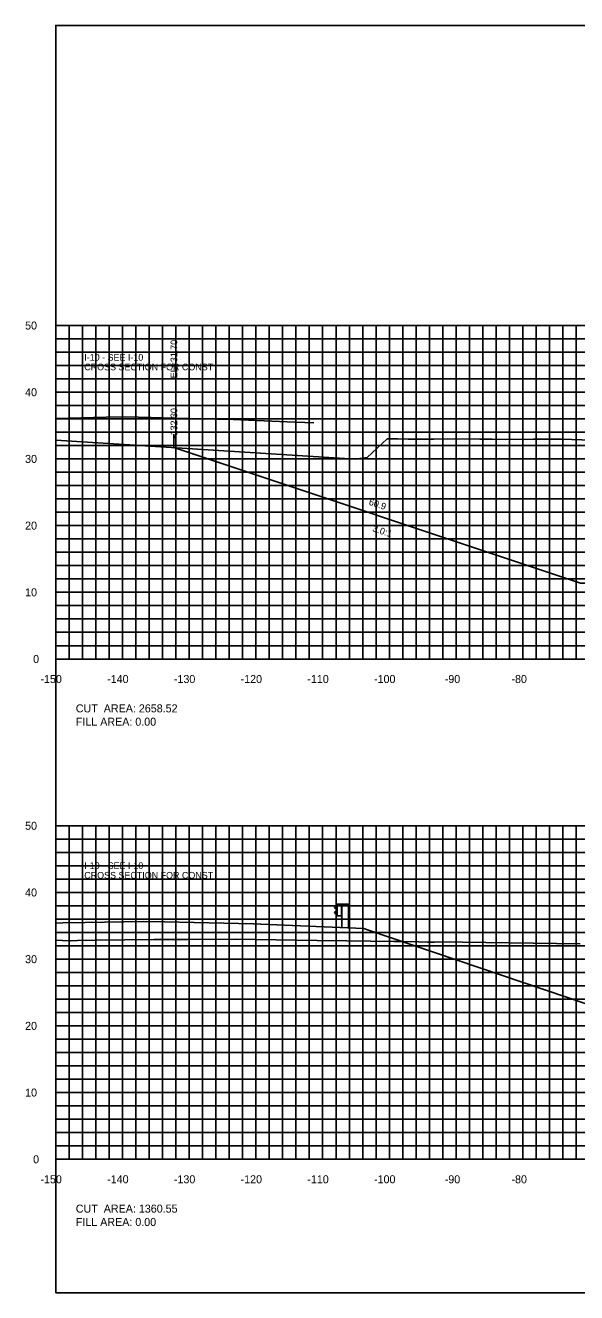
# Model space of a CAD drawing. Extents: x 1800976 to 1805104, y 250057 to 250580.
# Drawn here: x 1804176.4 to 1804259.1, y 250079.4 to 250269.4 of the extents above; entities that cross this region are included whole.
import ezdxf

# ---------------------------------------------------------------- set-up
doc = ezdxf.new("R2010")
doc.units = 0
for name, color, linetype in [('10', 7, 'Continuous'), ('3', 7, 'Continuous'), ('31', 7, 'Continuous'), ('4', 7, 'Continuous'), ('60', 7, 'Continuous'), ('ANNO-TXT', 7, 'Continuous'), ('CL-CNST', 7, 'Continuous'), ('Level 1', 7, 'Continuous'), ('Level 62', 7, 'Continuous'), ('M-ROADS', 7, 'Continuous')]:
    doc.layers.add(name, color=color, linetype=linetype)

msp = doc.modelspace()

# ---------------------------------------------------------------- linework, layer by layer
msp.add_line((1804198.7, 250206.13), (1804198.7, 250208.13))
msp.add_lwpolyline([(1804181, 250079.43), (1804481, 250079.43), (1804481, 250269.43), (1804181, 250269.43)], close=True)
at = {"layer": '60'}
for p, q in [((1804180.94, 250224.43), (1804181, 250224.43)), ((1804181, 250174.43), (1804181, 250224.43)), ((1804180.94, 250214.43), (1804181, 250214.43)), ((1804180.94, 250204.43), (1804181, 250204.43)), ((1804180.94, 250194.43), (1804181, 250194.43)), ((1804180.94, 250184.43), (1804181, 250184.43)), ((1804180.94, 250174.43), (1804181, 250174.43)), ((1804181, 250174.43), (1804481, 250174.43)), ((1804181, 250174.37), (1804181, 250174.43)), ((1804191, 250174.37), (1804191, 250174.43)), ((1804201, 250174.37), (1804201, 250174.43)), ((1804211, 250174.37), (1804211, 250174.43)), ((1804221, 250174.37), (1804221, 250174.43)), ((1804231, 250174.37), (1804231, 250174.43)), ((1804241, 250174.37), (1804241, 250174.43)), ((1804251, 250174.37), (1804251, 250174.43)), ((1804180.94, 250149.43), (1804181, 250149.43)), ((1804181, 250099.43), (1804181, 250149.43)), ((1804180.94, 250139.43), (1804181, 250139.43)), ((1804180.94, 250129.43), (1804181, 250129.43)), ((1804180.94, 250119.43), (1804181, 250119.43)), ((1804180.94, 250109.43), (1804181, 250109.43)), ((1804180.94, 250099.43), (1804181, 250099.43)), ((1804181, 250099.43), (1804481, 250099.43)), ((1804181, 250099.37), (1804181, 250099.43)), ((1804191, 250099.37), (1804191, 250099.43)), ((1804201, 250099.37), (1804201, 250099.43)), ((1804211, 250099.37), (1804211, 250099.43)), ((1804221, 250099.37), (1804221, 250099.43)), ((1804231, 250099.37), (1804231, 250099.43)), ((1804241, 250099.37), (1804241, 250099.43)), ((1804251, 250099.37), (1804251, 250099.43))]:
    msp.add_line(p, q, dxfattribs=at)
at = {"layer": 'CL-CNST'}
for points in [[(1804181, 250210.51), (1804188.54, 250210.67), (1804191.48, 250210.72), (1804202.84, 250210.46), (1804207.59, 250210.34), (1804215.66, 250210.01), (1804219.66, 250209.84)], [(1804198.7, 250206.13), (1804259.65, 250185.81), (1804263.65, 250185.81), (1804284.65, 250189.31), (1804290.23, 250189.54), (1804294.23, 250189.7), (1804326.41, 250188.99), (1804326.81, 250188.98), (1804331, 250188.89), (1804356.21, 250188.33), (1804364.21, 250188.01), (1804366.76, 250187.91), (1804390.76, 250181.91), (1804394.76, 250181.91), (1804405.91, 250184.7)], [(1804181, 250134.82), (1804182.05, 250134.86), (1804185.41, 250134.93), (1804194.11, 250135.1), (1804197.29, 250135.03), (1804210.64, 250134.71), (1804211.75, 250134.66), (1804227.18, 250134.02)], [(1804227.18, 250134.02), (1804227.88, 250133.78), (1804280.75, 250115.88), (1804282.94, 250115.88), (1804285.24, 250115.88)]]:
    msp.add_lwpolyline(points, dxfattribs=at)
at = {"layer": 'Level 1'}
for p, q in [((1804223.13, 250137.53), (1804222.76, 250137.23)), ((1804222.76, 250137.16), (1804223.13, 250136.87)), ((1804223.13, 250137.68), (1804223.13, 250135.93)), ((1804224.88, 250137.68), (1804223.13, 250137.68)), ((1804223.18, 250137.68), (1804223.18, 250135.93)), ((1804223.83, 250137.68), (1804223.83, 250135.93)), ((1804223.88, 250137.68), (1804223.88, 250134.15)), ((1804224.88, 250137.68), (1804224.88, 250134.11)), ((1804223.13, 250136.73), (1804222.76, 250136.44)), ((1804222.76, 250136.36), (1804223.13, 250136.08)), ((1804223.88, 250135.93), (1804223.13, 250135.93))]:
    msp.add_line(p, q, dxfattribs=at)
for centre in [(1804222.8, 250137.2), (1804222.8, 250136.4)]:
    msp.add_arc(centre, 0.05, 135, 226.6208, dxfattribs=at)
at = {"layer": 'Level 62'}
for p, q in [((1804181, 250224.43), (1804481, 250224.43)), ((1804181, 250174.43), (1804181, 250224.43)), ((1804183, 250174.43), (1804183, 250224.43)), ((1804185, 250174.43), (1804185, 250224.43)), ((1804187, 250174.43), (1804187, 250224.43)), ((1804189, 250174.43), (1804189, 250224.43)), ((1804191, 250174.43), (1804191, 250224.43)), ((1804193, 250174.43), (1804193, 250224.43)), ((1804195, 250174.43), (1804195, 250224.43)), ((1804197, 250174.43), (1804197, 250224.43)), ((1804199, 250174.43), (1804199, 250224.43)), ((1804201, 250174.43), (1804201, 250224.43)), ((1804203, 250174.43), (1804203, 250224.43)), ((1804205, 250174.43), (1804205, 250224.43)), ((1804207, 250174.43), (1804207, 250224.43)), ((1804209, 250174.43), (1804209, 250224.43)), ((1804211, 250174.43), (1804211, 250224.43)), ((1804213, 250174.43), (1804213, 250224.43)), ((1804215, 250174.43), (1804215, 250224.43)), ((1804217, 250174.43), (1804217, 250224.43)), ((1804219, 250174.43), (1804219, 250224.43)), ((1804221, 250174.43), (1804221, 250224.43)), ((1804223, 250174.43), (1804223, 250224.43)), ((1804225, 250174.43), (1804225, 250224.43)), ((1804227, 250174.43), (1804227, 250224.43)), ((1804229, 250174.43), (1804229, 250224.43)), ((1804231, 250174.43), (1804231, 250224.43)), ((1804233, 250174.43), (1804233, 250224.43)), ((1804235, 250174.43), (1804235, 250224.43)), ((1804237, 250174.43), (1804237, 250224.43)), ((1804239, 250174.43), (1804239, 250224.43)), ((1804241, 250174.43), (1804241, 250224.43)), ((1804243, 250174.43), (1804243, 250224.43)), ((1804245, 250174.43), (1804245, 250224.43)), ((1804247, 250174.43), (1804247, 250224.43)), ((1804249, 250174.43), (1804249, 250224.43)), ((1804251, 250174.43), (1804251, 250224.43)), ((1804253, 250174.43), (1804253, 250224.43)), ((1804255, 250174.43), (1804255, 250224.43)), ((1804257, 250174.43), (1804257, 250224.43)), ((1804259, 250174.43), (1804259, 250224.43)), ((1804181, 250222.43), (1804481, 250222.43)), ((1804181, 250220.43), (1804481, 250220.43)), ((1804181, 250218.43), (1804481, 250218.43)), ((1804181, 250216.43), (1804481, 250216.43)), ((1804181, 250214.43), (1804481, 250214.43)), ((1804181, 250212.43), (1804481, 250212.43)), ((1804181, 250210.43), (1804481, 250210.43)), ((1804181, 250208.43), (1804481, 250208.43)), ((1804181, 250206.43), (1804481, 250206.43)), ((1804181, 250204.43), (1804481, 250204.43)), ((1804181, 250202.43), (1804481, 250202.43)), ((1804181, 250200.43), (1804481, 250200.43)), ((1804181, 250198.43), (1804481, 250198.43)), ((1804181, 250196.43), (1804481, 250196.43)), ((1804181, 250194.43), (1804481, 250194.43)), ((1804181, 250192.43), (1804481, 250192.43)), ((1804181, 250190.43), (1804481, 250190.43)), ((1804181, 250188.43), (1804481, 250188.43)), ((1804181, 250186.43), (1804481, 250186.43)), ((1804181, 250184.43), (1804481, 250184.43)), ((1804181, 250182.43), (1804481, 250182.43)), ((1804181, 250180.43), (1804481, 250180.43)), ((1804181, 250178.43), (1804481, 250178.43)), ((1804181, 250176.43), (1804481, 250176.43)), ((1804181, 250174.43), (1804481, 250174.43)), ((1804181, 250149.43), (1804481, 250149.43)), ((1804181, 250099.43), (1804181, 250149.43)), ((1804183, 250099.43), (1804183, 250149.43)), ((1804185, 250099.43), (1804185, 250149.43)), ((1804187, 250099.43), (1804187, 250149.43)), ((1804189, 250099.43), (1804189, 250149.43)), ((1804191, 250099.43), (1804191, 250149.43)), ((1804193, 250099.43), (1804193, 250149.43)), ((1804195, 250099.43), (1804195, 250149.43)), ((1804197, 250099.43), (1804197, 250149.43)), ((1804199, 250099.43), (1804199, 250149.43)), ((1804201, 250099.43), (1804201, 250149.43)), ((1804203, 250099.43), (1804203, 250149.43)), ((1804205, 250099.43), (1804205, 250149.43)), ((1804207, 250099.43), (1804207, 250149.43)), ((1804209, 250099.43), (1804209, 250149.43)), ((1804211, 250099.43), (1804211, 250149.43)), ((1804213, 250099.43), (1804213, 250149.43)), ((1804215, 250099.43), (1804215, 250149.43)), ((1804217, 250099.43), (1804217, 250149.43)), ((1804219, 250099.43), (1804219, 250149.43)), ((1804221, 250099.43), (1804221, 250149.43)), ((1804223, 250099.43), (1804223, 250149.43)), ((1804225, 250099.43), (1804225, 250149.43)), ((1804227, 250099.43), (1804227, 250149.43)), ((1804229, 250099.43), (1804229, 250149.43)), ((1804231, 250099.43), (1804231, 250149.43)), ((1804233, 250099.43), (1804233, 250149.43)), ((1804235, 250099.43), (1804235, 250149.43)), ((1804237, 250099.43), (1804237, 250149.43)), ((1804239, 250099.43), (1804239, 250149.43)), ((1804241, 250099.43), (1804241, 250149.43)), ((1804243, 250099.43), (1804243, 250149.43)), ((1804245, 250099.43), (1804245, 250149.43)), ((1804247, 250099.43), (1804247, 250149.43)), ((1804249, 250099.43), (1804249, 250149.43)), ((1804251, 250099.43), (1804251, 250149.43)), ((1804253, 250099.43), (1804253, 250149.43)), ((1804255, 250099.43), (1804255, 250149.43)), ((1804257, 250099.43), (1804257, 250149.43)), ((1804259, 250099.43), (1804259, 250149.43)), ((1804181, 250147.43), (1804481, 250147.43)), ((1804181, 250145.43), (1804481, 250145.43)), ((1804181, 250143.43), (1804481, 250143.43)), ((1804181, 250141.43), (1804481, 250141.43)), ((1804181, 250139.43), (1804481, 250139.43)), ((1804181, 250137.43), (1804481, 250137.43)), ((1804181, 250135.43), (1804481, 250135.43)), ((1804181, 250133.43), (1804481, 250133.43)), ((1804181, 250131.43), (1804481, 250131.43)), ((1804181, 250129.43), (1804481, 250129.43)), ((1804181, 250127.43), (1804481, 250127.43)), ((1804181, 250125.43), (1804481, 250125.43)), ((1804181, 250123.43), (1804481, 250123.43)), ((1804181, 250121.43), (1804481, 250121.43)), ((1804181, 250119.43), (1804481, 250119.43)), ((1804181, 250117.43), (1804481, 250117.43)), ((1804181, 250115.43), (1804481, 250115.43)), ((1804181, 250113.43), (1804481, 250113.43)), ((1804181, 250111.43), (1804481, 250111.43)), ((1804181, 250109.43), (1804481, 250109.43)), ((1804181, 250107.43), (1804481, 250107.43)), ((1804181, 250105.43), (1804481, 250105.43)), ((1804181, 250103.43), (1804481, 250103.43)), ((1804181, 250101.43), (1804481, 250101.43)), ((1804181, 250099.43), (1804481, 250099.43))]:
    msp.add_line(p, q, dxfattribs=at)
at = {"layer": 'M-ROADS'}
for points in [[(1804181, 250207.25), (1804225.85, 250204.4), (1804227.69, 250204.65), (1804230.68, 250207.43), (1804232.25, 250207.42), (1804233.84, 250207.4), (1804235.07, 250207.39), (1804235.64, 250207.38), (1804237.65, 250207.41), (1804239.77, 250207.43), (1804244.55, 250207.4), (1804246.39, 250207.4), (1804248.45, 250207.35), (1804252.53, 250207.38), (1804254.94, 250207.38), (1804256.82, 250207.38), (1804261.4, 250207.23)], [(1804181, 250132.3), (1804183.02, 250132.19), (1804183.22, 250132.2), (1804184.27, 250132.22), (1804187.02, 250132.26), (1804195.71, 250132.38), (1804200.8, 250132.39), (1804207.95, 250132.41), (1804210.94, 250132.37), (1804220.19, 250132.22), (1804224.64, 250132.18), (1804231.71, 250132.08), (1804231.89, 250132.08), (1804232.96, 250132.06), (1804235.35, 250132.02), (1804236.71, 250132), (1804236.94, 250131.99), (1804237.77, 250131.99), (1804238.43, 250132.02), (1804259.59, 250131.75)]]:
    msp.add_lwpolyline(points, dxfattribs=at)

# ---------------------------------------------------------------- texts
msp.add_text('3.0:1', height=1, rotation=341.5651).set_placement((1804228.39, 250193.6))
at = {"layer": '10'}
for s, p in [('-150', (1804178.7, 250170.83)), ('-140', (1804188.7, 250170.83)), ('-130', (1804198.7, 250170.83)), ('-120', (1804208.7, 250170.83)), ('-110', (1804218.7, 250170.83)), ('-100', (1804228.7, 250170.83)), ('-90', (1804239.3, 250170.83)), ('-80', (1804249.3, 250170.83)), ('-150', (1804178.7, 250095.83)), ('-140', (1804188.7, 250095.83)), ('-130', (1804198.7, 250095.83)), ('-120', (1804208.7, 250095.83)), ('-110', (1804218.7, 250095.83)), ('-100', (1804228.7, 250095.83)), ('-90', (1804239.3, 250095.83)), ('-80', (1804249.3, 250095.83))]:
    msp.add_text(s, height=1.2, dxfattribs=at).set_placement(p)
at = {"layer": '3'}
for s, p in [('EL=31.70', (1804199.2, 250216.52)), ('-132.30', (1804199.2, 250207.51))]:
    msp.add_text(s, height=1, rotation=90, dxfattribs=at).set_placement(p)
for s, p in [('CROSS SECTION FOR CONST ', (1804185.27, 250217.72)), ('I-10 - SEE I-10 ', (1804185.27, 250219.16)), ('I-10 - SEE I-10 ', (1804185.27, 250142.95)), ('CROSS SECTION FOR CONST ', (1804185.27, 250141.51))]:
    msp.add_text(s, height=1, dxfattribs=at).set_placement(p)
at = {"layer": '31'}
for s, p in [('50', (1804176.4, 250223.83)), ('40', (1804176.4, 250213.83)), ('30', (1804176.4, 250203.83)), ('20', (1804176.4, 250193.83)), ('10', (1804176.4, 250183.83)), ('0', (1804177.6, 250173.83)), ('50', (1804176.4, 250148.83)), ('40', (1804176.4, 250138.83)), ('30', (1804176.4, 250128.83)), ('20', (1804176.4, 250118.83)), ('10', (1804176.4, 250108.83)), ('0', (1804177.6, 250098.83))]:
    msp.add_text(s, height=1.2, dxfattribs=at).set_placement(p)
at = {"layer": '4'}
msp.add_text('60.9', height=1, rotation=341.5651, dxfattribs=at).set_placement((1804227.84, 250197.58))
at = {"layer": '60'}
for p in [(1804181, 250174.43), (1804181, 250099.43)]:
    msp.add_text('-', height=0.0001, dxfattribs=at).set_placement(p)
at = {"layer": 'ANNO-TXT'}
for s, p in [('CUT  AREA: 2658.52', (1804184, 250166.43)), ('FILL AREA: 0.00', (1804184, 250164.43)), ('CUT  AREA: 1360.55', (1804184, 250091.43)), ('FILL AREA: 0.00', (1804184, 250089.43))]:
    msp.add_text(s, height=1.2, dxfattribs=at).set_placement(p)

doc.saveas('drawing.dxf')
